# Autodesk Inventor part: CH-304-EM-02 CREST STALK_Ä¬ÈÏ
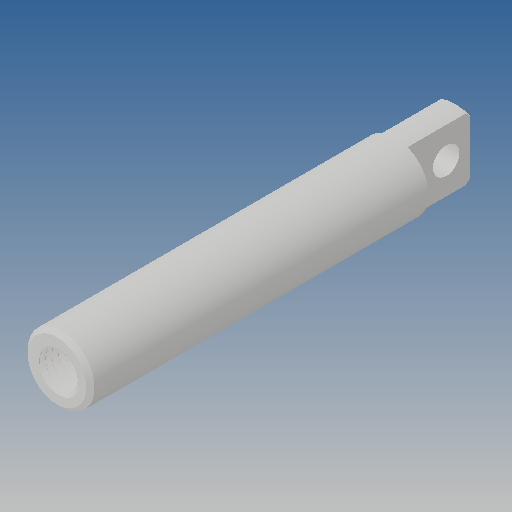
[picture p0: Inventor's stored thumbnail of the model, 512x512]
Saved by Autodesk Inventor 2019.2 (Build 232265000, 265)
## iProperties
Created: 2010-06
Part Number: CH-304-EM-02 CREST STALK_Ä¬ÈÏ
Material: Ogólny
Document SubType Name: Modeling
Designer: CADENGINEERING4
Density: 1 g/cm^3
Appearance: Domyślna
Author: CADENGINEERING4
Revision Number: ÈÎºÎ
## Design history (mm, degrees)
feature "NONE"
node "Bryła1"
